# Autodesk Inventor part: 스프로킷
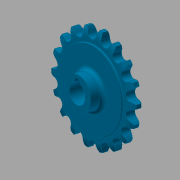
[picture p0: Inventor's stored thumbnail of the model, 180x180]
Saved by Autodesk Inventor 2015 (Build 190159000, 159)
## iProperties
Created: 2016-03
Part Number: 스프로킷
Material: 강철, 탄소
Document SubType Name: Modeling
Designer: mduedu
Density: 7.87 g/cm^3
Mass: 301.818 g
Surface Area: 124.882 cm^2
Volume: 38.3505 cm^3
Appearance: 하늘색 중간
Author: mduedu
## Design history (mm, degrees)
sketch "스케치1"
  geometry: L1 (0, 5)-(29.5, 5); L2 (29.5, 5)-(29.5, 4.1); L3 (30, 3.6)-(33.625, 3.6); L4 (40, 2)-(40, 0); L5 (40, 0)-(0, 0); L6 (0, 0)-(0, 5); L7 (0, -5)-(29.5, -5); L8 (29.5, -5)-(29.5, -4.1); L9 (30, -3.6)-(33.625, -3.6); L10 (40, -2)-(40, 0); L11 (0, 0)-(0, -5); A1 r 13.5 centre (33.625, -9.9) between (40, 2) and (33.625, 3.6); A2 r 13.5 centre (33.625, 9.9) between (33.625, -3.6) and (40, -2); A3 r 0.5 centre (30, 4.1) between (29.5, 4.1) and (30, 3.6); A4 r 0.5 centre (30, -4.1) between (30, -3.6) and (29.5, -4.1); 2 further points
  constraints: 22 end point, 8 point on circle, 6 symmetric about line, 5 tangent, 4 centre point, 4 parallel, 4 point on line, 1 equal radius, 1 horizontal, 1 perpendicular, 1 other
  dimensions: "d0" = 80 diameter of L4 L6; "d2" = 59 diameter of L2 L6; "d3" = 1.6 vertical distance of L4.start L3.end; "d4" = 3.6 distance from line of L4.end L3; "d5" = 5 distance between parallel lines of L5 L1; "d6" = 13.5 radius of A1; "d15" = 0.5 radius of A3
revolve "회전1" sketch "스케치1" stored, may be unused: angle "d7" = 90 deg
sketch "스케치2" dims "d8" = 65.2, "d11" = 80
  geometry: L1 (0, 0)-(0, 32.6); A1 r 36.57 centre (0, 0) between (-16.231, 32.771) and (0, 36.57); A2 r 3.97 centre (0, 36.57) between (-3.866, 35.665) and (0, 32.6); A3 r 12.7 centre (-16.231, 32.771) between (-3.866, 35.665) and (-5.534, 39.615); A4 r 12.7 centre (16.231, 32.771) between (5.534, 39.615) and (3.866, 35.665); A5 r 3.97 centre (0, 36.57) between (0, 32.6) and (3.866, 35.665); A6 r 40 centre (0, 0) between (5.534, 39.615) and (-5.534, 39.615); 2 further points
  constraints: 12 point on circle, 6 centre point, 4 coincident, 3 symmetric about line, 2 end point, 1 point on line, 1 tangent, 1 vertical, 1 vertical alignment, 7 other
  dimensions: "d10" = 73.14 diameter of A1; "d12" = 12.7 radius of A3
extrude "돌출1" cut sketch "스케치2" stored distance "d13" = 10; taper "d14" = 0 deg
sketch "스케치3"
  geometry: C1 r 12.5 at (0, 0); 1 further point
  constraints: 1 centre point, 1 coincident
  dimensions: "d19" = 25 diameter of C1
extrude "돌출2" join sketch "스케치3" distance "d20" = 10; taper "d21" = 0 deg
fillet "모깎기1" dims "d22" = 3
sketch "스케치4"
  geometry: L1 (-2.5, 0)-(2.5, 0); L2 (2.5, 0)-(2.5, 9.8); L3 (2.5, 9.8)-(-2.5, 9.8); L4 (-2.5, 9.8)-(-2.5, 0); C1 r 7.5 at (0, 0); 2 further points
  constraints: 8 end point, 2 coincident, 2 parallel, 1 centre point, 1 horizontal, 1 midpoint, 1 perpendicular
  dimensions: "d23" = 15 diameter of C1; "d25" = 5 distance of L2.end L3.end; "d26" = 9.8 distance of L1.end L2.end
extrude "돌출3" cut sketch "스케치4" stored distance "d27" = 8; taper "d28" = 0 deg
node "솔리드1"
pattern_circular "원형 패턴1" dims angle "d17" = 360 deg
